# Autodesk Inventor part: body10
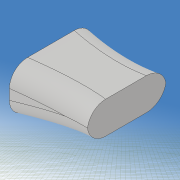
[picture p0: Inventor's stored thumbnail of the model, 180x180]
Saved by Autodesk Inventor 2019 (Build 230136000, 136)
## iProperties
Created: 2020-12
Part Number: body10
Material: 一般
Document SubType Name: Modeling
Designer: kikut
Density: 1 g/cm^3
Appearance: 既定
Mass: 87.6477 g
Surface Area: 156.124 cm^2
Volume: 87.6477 cm^3
Author: kikut
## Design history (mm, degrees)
sketch "スケッチ1"
  geometry: L1 (-100, -20)-(100, -20); L2 (100, -20)-(100, 20); L3 (100, 20)-(-100, 20); L4 (-100, 20)-(-100, -20); L5 (-100, -20)-(100, 20); L6 (100, -20)-(-100, 20); 1 further point
  constraints: 12 end point, 2 midpoint, 2 parallel, 1 horizontal, 1 perpendicular
  dimensions: "d0" = 40 distance of L3.end L1.start; "d1" = 200 distance of L2.end L3.end
extrude "押し出し1" new body sketch "スケッチ1" stored distance "d2" = 60; taper "d3" = 0 deg
sketch "スケッチ2"
  geometry: L1 (0, -60)-(0, 0) reference; L2 (200, -60)-(200, 0) reference; L3 (0, 0)-(200, 0) reference; L4 (200, -60)-(0, -60) reference; L5 (0, -26)-(0, -32); L6 (194, -10)-(194, -13); L7 (194, -13)-(174, -33); L8 (174, -33)-(200, -58); L9 (-20, 20)-(220, 20); L10 (220, 20)-(220, -100); L11 (220, -100)-(-20, -100); L12 (-20, -100)-(-20, 20); 12 further points
  constraints: 16 end point, 4 point on line, 2 parallel, 2 vertical, 1 horizontal, 1 perpendicular, 14 other
  dimensions: "d4" = 32 distance from line of point (32, -12) L1; "d5" = 50 horizontal distance of point (32, -12) point (82, -11); "d6" = 50 horizontal distance of point (132, -17) point (82, -11); "d7" = 12 distance from line of point (32, -12) L3; "d8" = 11 distance from line of point (82, -11) L3; "d10" = 17 distance from line of point (132, -17) L3; "d11" = 26 distance from line of L5.start L3; "d12" = 0 distance from line of point (200, -60) L4; "d13" = 28 distance from line of L5.end L4; "d14" = 12 distance from line of point (28, -48) L4; "d15" = 10 distance from line of point (80, -50) L4; "d16" = 16 distance from line of point (130, -44) L4; "d17" = 28 distance from line of point (28, -48) L1; "d19" = 50 horizontal distance of point (130, -44) point (80, -50); "d20" = 80 distance from line of point (80, -50) L1; "d21" = 6 distance from line of L6.start L2; "d22" = 36 distance from line of point (164, -24) L2; "d23" = 24 distance from line of point (176, -20) L2; "d24" = 10 distance from line of L6.start L3; "d25" = 20 distance from line of point (176, -20) L3; "d26" = 24 distance from line of point (164, -24) L3; "d27" = 40 distance from line of point (160, -40) L2; "d28" = 25 distance from line of point (175, -47.5) L2; "d29" = 12.5 distance from line of point (175, -47.5) L4; "d30" = 20 distance from line of L4 point (160, -40); "d31" = 3 distance of L6.start L6.end; "d32" = 33 distance from line of L7.end L3; "d33" = 26 distance from line of L7.end L2; "d34" = 2 distance of L8.end L2.start; "d35" = 120 distance of L11.end L9.start; "d36" = 240 distance of L10.end L11.end; "d37" = 20 distance between parallel lines of L1 L12; "d38" = 20 distance between parallel lines of L3 L9
extrude "押し出し2" cut sketch "スケッチ2" extent not by distance; stored distance "d39" = 0.02; taper "d40" = 0 deg
sketch "スケッチ8"
  geometry: L1 (-100, -20)-(-100, 20) reference; L2 (100, 20)-(100, -20) reference; L3 (-142.805, 0)-(142.831, 0) reference; L4 (110, 30)-(-110, 30); L5 (-110, 30)-(-110, -30); L6 (-110, -30)-(110, -30); L7 (110, -30)-(110, 30); L8 (110, 30)-(-110, -30); L9 (-110, 30)-(110, -30); L10 (-100, -2)-(-100, 2); L11 (100, -3)-(100, 3); 7 further points
  constraints: 16 end point, 4 point on line, 2 midpoint, 2 parallel, 2 perpendicular, 1 collinear, 1 horizontal, 10 other
  dimensions: "d93" = 2 vertical distance of point (0, 0) L10.end; "d94" = 2 vertical distance of L10.start point (0, 0); "d95" = 35 distance from line of point (-65, -10) L1; "d96" = 0 horizontal distance of point (-65, 10) point (-65, -10); "d97" = 10 vertical distance of point (0, 0) point (-65, -10); "d98" = 10 vertical distance of point (-65, 10) point (0, 0); "d99" = 100 distance from line of point (0, -10) L1; "d100" = 0 horizontal distance of point (0, 10) point (0, -10); "d101" = 10 distance of point (0, -10) point (0, 0); "d102" = 10 distance of point (0, 0) point (0, 10); "d103" = 160 distance from line of point (60, -4) L1; "d104" = 0 horizontal distance of point (60, 4) point (60, -4); "d105" = 4 distance from line of L3 point (60, -4); "d106" = 4 distance from line of L3 point (60, 4); "d107" = 3 distance from line of L11.start L3; "d108" = 3 distance from line of L11.end L3; "d109" = 220 distance of L5.end L6.end; "d110" = 60 distance of L4.end L5.end
extrude "押し出し6" cut sketch "スケッチ8" extent not by distance; stored distance "d111" = 10; taper "d112" = 0 deg
sketch "スケッチ9" dims "d113" = 20, "d114" = 12
  geometry: L1 (-29, -18)-(21, -18); L2 (21, -18)-(21, 22); L3 (21, 22)-(-29, 22); L4 (-29, 22)-(-29, -18); L5 (-29, -18)-(21, 22); L6 (21, -18)-(-29, 22); 2 further points; 1 other entity
  constraints: 12 end point, 2 midpoint, 2 parallel, 1 coincident, 1 horizontal, 1 perpendicular, 2 other
  dimensions: "d115" = 50 distance of L2.end L3.end; "d116" = 40 distance of L1.end L2.end
extrude "押し出し7" cut sketch "スケッチ9" distance "d117" = 150; taper "d118" = 0 deg
fillet "フィレット4" dims "d119" = 4
fillet "フィレット5" dims "d120" = 4
fillet "フィレット6" dims "d121" = 2
node "作業平面2"
sketch "スケッチ10"
  geometry: L1 (0, -41.439)-(0, 38.458) reference; L2 (141.833, 0)-(-140.631, 0) reference; L3 (82.55, 12.983)-(81.45, -4.983); A1 r 9 centre (82, 4) between (82.55, 12.983) and (81.45, -4.983); 1 further point
  constraints: 2 end point, 2 point on circle, 1 centre point
  dimensions: "d123" = 82 distance from line of L1 A1.centre; "d124" = 4 distance from line of L2 A1.centre; "d125" = 9 radius of A1; "d126" = 180 deg dimension on A1.centre L3.end L3.start; "d127" = 90 deg dimension on L3.end point (0, 0) A1.centre
revolve "回転1" sketch "スケッチ10" stored, may be unused: angle "d128" = 90 deg
mirror "ミラー1"
sketch "スケッチ11"
  geometry: L1 (-50, 30)-(-65, 30); L2 (-65, 30)-(-65, -30); L3 (-65, -30)-(-50, -30); L4 (-50, -30)-(-50, 30); L5 (0, -40.648)-(0, 34.486) reference; L6 (140.69, 0)-(-139.196, 0) reference; L7 (120, 53.792)-(-120, 53.792); L8 (-120, 53.792)-(-120, -46.208); L9 (-120, -46.208)-(120, -46.208); L10 (120, -46.208)-(120, 53.792); 1 further point
  constraints: 16 end point, 4 parallel, 2 horizontal, 2 perpendicular, 2 other
  dimensions: "d130" = 15 distance of L1.start L1.end; "d131" = 60 distance of L3.end L1.start; "d132" = 100 distance of L9.end L7.start; "d133" = 240 distance of L7.start L7.end; "d137" = 65 distance between parallel lines of L2 L5
extrude "押し出し8" cut sketch "スケッチ11" stored distance "d134" = 40; taper "d135" = 0 deg
node "ソリッド1"
other parameters: "d122" = -1
